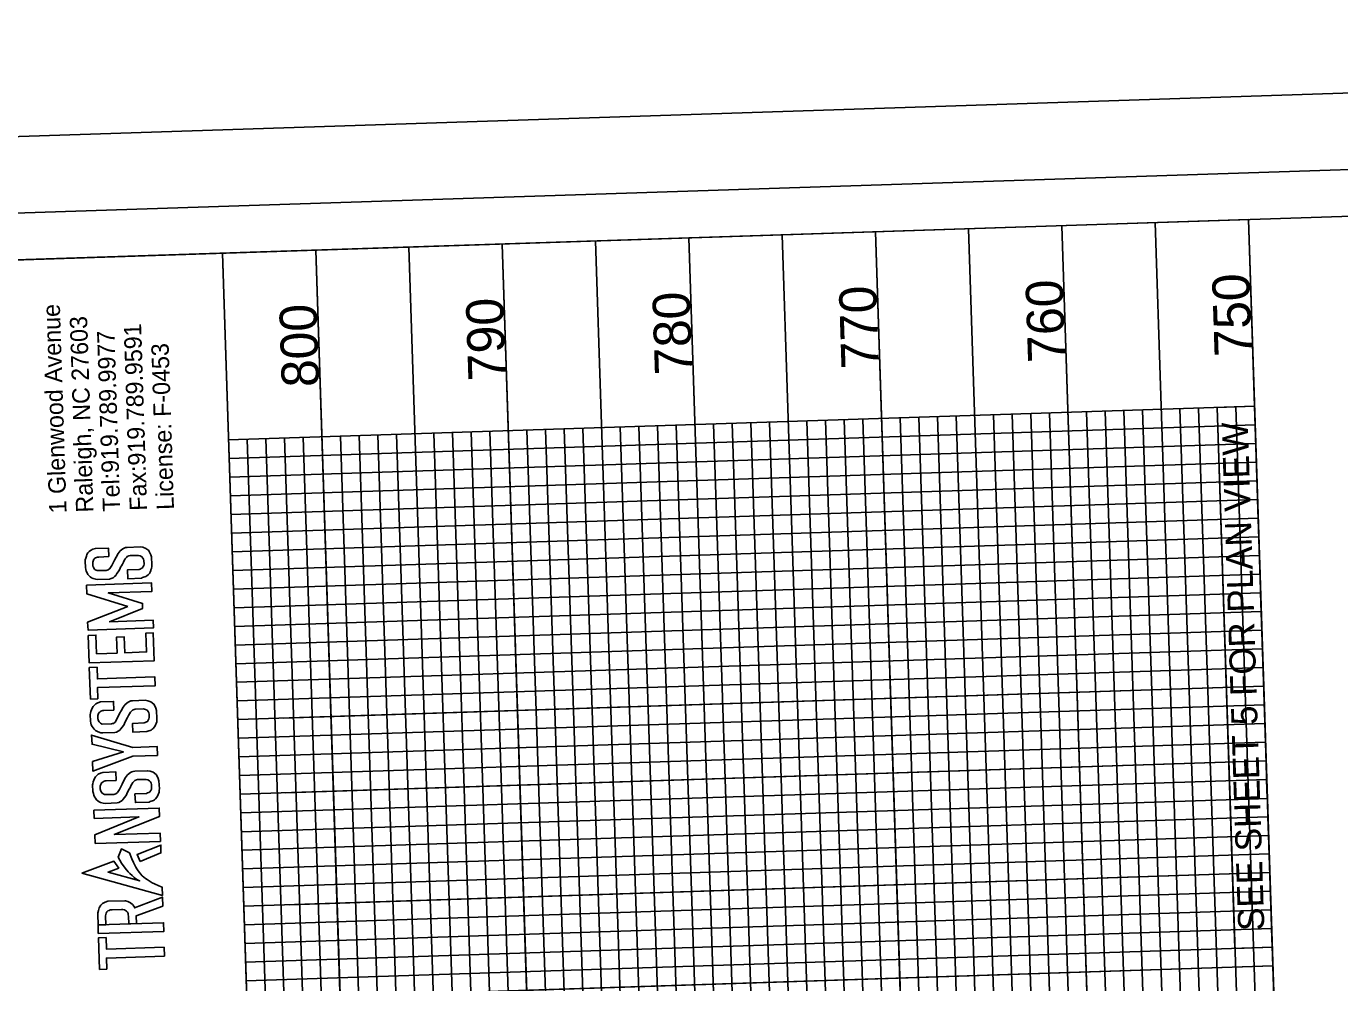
# Model space of a CAD drawing. Extents: x 1627314 to 1628469, y 762309 to 764247.
# Drawn here: x 1627512.6 to 1627864.5, y 763788.2 to 764044.4 of the extents above; entities that cross this region are included whole.
import ezdxf

# ---------------------------------------------------------------- set-up
doc = ezdxf.new("R2010")
doc.units = 0
for name, color, linetype in [('Exist Vertical Profile Vertical Axis Label', 7, 'Continuous'), ('Old_Level_2', 7, 'Continuous'), ('Prop DSN Text', 7, 'Continuous'), ('Prop Grid Mask', 7, 'Continuous'), ('Sheet DOT Grid CELL', 7, 'Continuous'), ('Sheet Layout Profile Border Port 1', 7, 'Continuous'), ('Sheet Plot Border Inside CELL', 7, 'Continuous'), ('Sheet Plot Border Outside CELL', 7, 'Continuous'), ('Sheet Profile CELL', 7, 'Continuous'), ('Sheet Profile Grid Major CELL', 7, 'Continuous'), ('Sheet Profile Grid Middle CELL', 7, 'Continuous'), ('Sheet Profile Grid Minor CELL', 7, 'Continuous')]:
    doc.layers.add(name, color=color, linetype=linetype)

msp = doc.modelspace()

# ---------------------------------------------------------------- linework, layer by layer
at = {"layer": 'Old_Level_2'}
for points in [[(1627507.79, 763781.61), (1627501.25, 763981.49), (1627565.16, 763983.58), (1627571.7, 763783.7)], [(1627534.7, 763902.32), (1627534.62, 763904.63), (1627531.15, 763904.51), (1627530.45, 763904.29), (1627529.87, 763903.99), (1627529.49, 763903.68), (1627529.15, 763903.3), (1627528.88, 763902.85), (1627528.72, 763902.42), (1627528.72, 763902.42), (1627528.54, 763901.95), (1627528.44, 763901.47), (1627528.37, 763901.14), (1627528.46, 763899.4), (1627528.57, 763898.87), (1627528.66, 763898.42), (1627528.92, 763897.96), (1627529.14, 763897.57), (1627529.44, 763897.18), (1627529.76, 763896.88), (1627530.13, 763896.65), (1627530.53, 763896.47), (1627531.24, 763896.24), (1627531.76, 763896.2), (1627534.92, 763896.31), (1627535.4, 763896.44), (1627535.88, 763896.68), (1627536.28, 763896.99), (1627536.58, 763897.29), (1627536.92, 763897.76), (1627537.25, 763898.22), (1627537.46, 763898.51), (1627537.67, 763899), (1627537.88, 763899.49), (1627538.12, 763899.89), (1627538.39, 763900.34), (1627538.64, 763900.87), (1627538.84, 763901.31), (1627539.14, 763901.75), (1627539.43, 763902.07), (1627539.66, 763902.33), (1627540.13, 763902.5), (1627540.43, 763902.6), (1627542.67, 763902.64), (1627543.16, 763902.5), (1627543.58, 763902.27), (1627543.88, 763901.95), (1627544.06, 763901.6), (1627544.14, 763901.26), (1627544.19, 763900.3), (1627544.11, 763899.97), (1627543.93, 763899.64), (1627543.75, 763899.3), (1627543.42, 763899.15), (1627543.09, 763899), (1627542.82, 763898.88), (1627539.71, 763898.74), (1627539.82, 763896.4), (1627543.52, 763896.57), (1627543.8, 763896.69), (1627544.65, 763896.99), (1627544.94, 763897.18), (1627545.25, 763897.44), (1627545.61, 763897.83), (1627545.8, 763898.14), (1627545.96, 763898.58), (1627546.03, 763898.74), (1627546.19, 763899.18), (1627546.23, 763899.72), (1627546.25, 763900.11), (1627546.13, 763902.25), (1627545.97, 763902.84), (1627545.57, 763903.65), (1627545.43, 763903.93), (1627544.62, 763904.52), (1627543.83, 763904.83), (1627543.11, 763904.96), (1627539.69, 763904.8), (1627539.22, 763904.77), (1627538.85, 763904.63), (1627538.5, 763904.43), (1627537.76, 763903.86), (1627537.23, 763903.14), (1627536.68, 763902.14), (1627536.26, 763901.39), (1627535.54, 763899.9), (1627535.01, 763899.13), (1627534.59, 763898.78), (1627534.31, 763898.7), (1627534.03, 763898.61), (1627531.6, 763898.58), (1627531.34, 763898.69), (1627531.08, 763898.81), (1627530.93, 763898.98), (1627530.72, 763899.21), (1627530.61, 763899.46), (1627530.49, 763899.72), (1627530.52, 763899.86), (1627530.44, 763899.88), (1627530.42, 763900.84), (1627530.53, 763901.12), (1627530.63, 763901.4), (1627530.73, 763901.68), (1627530.91, 763901.81), (1627531.19, 763902.01), (1627531.46, 763902.11), (1627531.73, 763902.21), (1627532.04, 763902.21)], [(1627539.83, 763888.95), (1627529.04, 763884.78), (1627529.22, 763882.58), (1627546.67, 763883.23), (1627546.59, 763885.34), (1627534.92, 763884.9), (1627543.79, 763888.46), (1627543.78, 763889.81), (1627534.56, 763892.58), (1627546.27, 763893), (1627546.19, 763895.28), (1627528.78, 763894.65), (1627528.86, 763892.35)], [(1627529.23, 763881.22), (1627529.48, 763873.84), (1627546.89, 763874.43), (1627546.64, 763881.9), (1627544.67, 763881.83), (1627544.84, 763876.79), (1627539, 763876.59), (1627538.86, 763880.8), (1627536.79, 763880.73), (1627536.93, 763876.49), (1627531.44, 763876.3), (1627531.27, 763881.31)], [(1627529.79, 763864.16), (1627529.51, 763872.62), (1627531.58, 763872.69), (1627531.69, 763869.58), (1627547.1, 763870.1), (1627547.18, 763867.75), (1627531.66, 763867.23), (1627531.76, 763864.26)], [(1627536.08, 763861.21), (1627536.01, 763863.52), (1627532.53, 763863.4), (1627531.83, 763863.18), (1627531.25, 763862.88), (1627530.87, 763862.57), (1627530.53, 763862.19), (1627530.26, 763861.74), (1627530.1, 763861.31), (1627530.1, 763861.31), (1627529.93, 763860.84), (1627529.82, 763860.36), (1627529.75, 763860.03), (1627529.84, 763858.29), (1627529.95, 763857.76), (1627530.04, 763857.31), (1627530.3, 763856.85), (1627530.52, 763856.46), (1627530.82, 763856.07), (1627531.14, 763855.77), (1627531.52, 763855.54), (1627531.92, 763855.36), (1627532.62, 763855.13), (1627533.14, 763855.09), (1627536.31, 763855.2), (1627536.78, 763855.33), (1627537.26, 763855.58), (1627537.67, 763855.88), (1627537.97, 763856.18), (1627538.3, 763856.65), (1627538.63, 763857.11), (1627538.84, 763857.4), (1627539.05, 763857.89), (1627539.26, 763858.38), (1627539.5, 763858.78), (1627539.77, 763859.23), (1627540.02, 763859.77), (1627540.23, 763860.21), (1627540.53, 763860.65), (1627540.81, 763860.96), (1627541.04, 763861.22), (1627541.52, 763861.39), (1627541.81, 763861.5), (1627544.05, 763861.53), (1627544.54, 763861.39), (1627544.97, 763861.16), (1627545.27, 763860.84), (1627545.44, 763860.49), (1627545.52, 763860.15), (1627545.57, 763859.19), (1627545.49, 763858.87), (1627545.31, 763858.53), (1627545.13, 763858.2), (1627544.8, 763858.04), (1627544.47, 763857.89), (1627544.21, 763857.77), (1627541.1, 763857.63), (1627541.2, 763855.29), (1627544.91, 763855.46), (1627545.19, 763855.58), (1627546.04, 763855.88), (1627546.32, 763856.07), (1627546.63, 763856.33), (1627547, 763856.72), (1627547.18, 763857.03), (1627547.35, 763857.48), (1627547.41, 763857.64), (1627547.58, 763858.07), (1627547.61, 763858.61), (1627547.64, 763859), (1627547.51, 763861.14), (1627547.35, 763861.73), (1627546.95, 763862.54), (1627546.82, 763862.82), (1627546.01, 763863.41), (1627545.21, 763863.72), (1627544.49, 763863.85), (1627541.08, 763863.69), (1627540.6, 763863.66), (1627540.23, 763863.52), (1627539.88, 763863.32), (1627539.14, 763862.75), (1627538.61, 763862.03), (1627538.06, 763861.04), (1627537.64, 763860.28), (1627536.92, 763858.79), (1627536.39, 763858.02), (1627535.98, 763857.67), (1627535.7, 763857.59), (1627535.42, 763857.5), (1627532.98, 763857.47), (1627532.73, 763857.58), (1627532.47, 763857.7), (1627532.31, 763857.87), (1627532.11, 763858.1), (1627531.99, 763858.35), (1627531.87, 763858.61), (1627531.9, 763858.75), (1627531.82, 763858.77), (1627531.81, 763859.73), (1627531.91, 763860.01), (1627532.01, 763860.29), (1627532.11, 763860.57), (1627532.3, 763860.7), (1627532.57, 763860.9), (1627532.84, 763861), (1627533.12, 763861.1), (1627533.42, 763861.1)], [(1627530.37, 763847.41), (1627530.45, 763844.88), (1627541.21, 763848.85), (1627547.75, 763849.09), (1627547.66, 763851.48), (1627541.17, 763851.24), (1627530.09, 763854.54), (1627530.24, 763852.05), (1627538.66, 763850.01)], [(1627536.72, 763842.35), (1627536.64, 763844.65), (1627533.16, 763844.54), (1627532.47, 763844.32), (1627531.89, 763844.02), (1627531.51, 763843.71), (1627531.17, 763843.33), (1627530.9, 763842.88), (1627530.74, 763842.45), (1627530.74, 763842.45), (1627530.56, 763841.98), (1627530.45, 763841.5), (1627530.38, 763841.17), (1627530.48, 763839.43), (1627530.59, 763838.9), (1627530.68, 763838.45), (1627530.93, 763837.99), (1627531.16, 763837.6), (1627531.46, 763837.21), (1627531.78, 763836.91), (1627532.15, 763836.68), (1627532.55, 763836.5), (1627533.26, 763836.27), (1627533.77, 763836.23), (1627536.94, 763836.34), (1627537.41, 763836.47), (1627537.9, 763836.71), (1627538.3, 763837.02), (1627538.6, 763837.32), (1627538.93, 763837.78), (1627539.27, 763838.25), (1627539.48, 763838.54), (1627539.69, 763839.03), (1627539.89, 763839.52), (1627540.13, 763839.92), (1627540.41, 763840.37), (1627540.66, 763840.9), (1627540.86, 763841.34), (1627541.16, 763841.78), (1627541.45, 763842.1), (1627541.68, 763842.36), (1627542.15, 763842.53), (1627542.45, 763842.63), (1627544.68, 763842.67), (1627545.17, 763842.53), (1627545.6, 763842.3), (1627545.9, 763841.98), (1627546.07, 763841.63), (1627546.16, 763841.29), (1627546.21, 763840.33), (1627546.13, 763840), (1627545.95, 763839.67), (1627545.76, 763839.33), (1627545.43, 763839.18), (1627545.1, 763839.03), (1627544.84, 763838.91), (1627541.73, 763838.77), (1627541.84, 763836.43), (1627545.54, 763836.6), (1627545.82, 763836.72), (1627546.67, 763837.02), (1627546.96, 763837.21), (1627547.27, 763837.47), (1627547.63, 763837.86), (1627547.81, 763838.17), (1627547.98, 763838.61), (1627548.04, 763838.77), (1627548.21, 763839.21), (1627548.25, 763839.75), (1627548.27, 763840.14), (1627548.15, 763842.28), (1627547.99, 763842.87), (1627547.59, 763843.68), (1627547.45, 763843.95), (1627546.64, 763844.55), (1627545.84, 763844.86), (1627545.13, 763844.99), (1627541.71, 763844.83), (1627541.24, 763844.8), (1627540.87, 763844.66), (1627540.52, 763844.46), (1627539.78, 763843.89), (1627539.24, 763843.17), (1627538.7, 763842.17), (1627538.28, 763841.42), (1627537.56, 763839.93), (1627537.02, 763839.15), (1627536.61, 763838.81), (1627536.33, 763838.73), (1627536.05, 763838.64), (1627533.62, 763838.61), (1627533.36, 763838.72), (1627533.1, 763838.84), (1627532.94, 763839.01), (1627532.74, 763839.23), (1627532.62, 763839.49), (1627532.51, 763839.75), (1627532.53, 763839.89), (1627532.46, 763839.91), (1627532.44, 763840.86), (1627532.54, 763841.15), (1627532.64, 763841.43), (1627532.74, 763841.71), (1627532.93, 763841.84), (1627533.2, 763842.04), (1627533.48, 763842.14), (1627533.75, 763842.24), (1627534.06, 763842.24)], [(1627531.1, 763825.45), (1627548.55, 763826.04), (1627548.47, 763828.28), (1627536.2, 763827.86), (1627548.35, 763832.72), (1627548.25, 763834.96), (1627530.75, 763834.37), (1627530.83, 763832.19), (1627542.8, 763832.6), (1627531.01, 763827.81)], [(1627527.54, 763817.56), (1627549.08, 763811.6), (1627548.99, 763813.82), (1627548.14, 763814.14), (1627546.97, 763814.67), (1627546.33, 763814.96), (1627545.78, 763815.32), (1627545, 763815.82), (1627544.52, 763816.13), (1627544.12, 763816.5), (1627543.71, 763816.86), (1627543.2, 763817.33), (1627542.92, 763817.74), (1627542.57, 763818.14), (1627542.23, 763818.69), (1627541.93, 763819.17), (1627541.33, 763820.37), (1627540.88, 763821.35), (1627540.27, 763822.98), (1627538.09, 763824.04), (1627537.21, 763821.84), (1627538.15, 763820.23), (1627539.1, 763818.89), (1627539.92, 763817.93), (1627540.37, 763817.42), (1627540.95, 763816.91), (1627541.54, 763816.39), (1627541.97, 763816.01), (1627542.63, 763815.65), (1627543, 763815.45), (1627534.54, 763817.81), (1627537.4, 763818.9), (1627536.08, 763820.75)], [(1627543.15, 763820.69), (1627542.32, 763822.58), (1627548.68, 763825.05), (1627548.67, 763822.95)], [(1627533.93, 763803.74), (1627533.85, 763806.13), (1627533.89, 763806.43), (1627534.04, 763806.84), (1627534.24, 763807.17), (1627534.51, 763807.41), (1627534.83, 763807.58), (1627535.09, 763807.71), (1627535.67, 763807.73), (1627538.16, 763807.82), (1627538.49, 763807.77), (1627538.94, 763807.7), (1627539.23, 763807.58), (1627539.5, 763807.38), (1627539.72, 763807.12), (1627539.89, 763806.7), (1627539.94, 763806.38), (1627539.99, 763806.05), (1627540.07, 763803.95), (1627542.18, 763804.03), (1627542.1, 763806.13), (1627549.18, 763808.74), (1627549.07, 763811.15), (1627541.63, 763808.25), (1627541.48, 763808.63), (1627541.06, 763809.15), (1627540.51, 763809.62), (1627539.87, 763809.95), (1627539.23, 763810.14), (1627539.04, 763810.12), (1627534.48, 763810.01), (1627533.74, 763809.79), (1627533.08, 763809.4), (1627532.62, 763808.98), (1627532.17, 763808.26), (1627531.96, 763807.58), (1627531.76, 763806.89), (1627531.77, 763806.49), (1627531.84, 763803.67)], [(1627531.92, 763801.36), (1627531.84, 763803.67), (1627549.4, 763804.26), (1627549.48, 763801.95)], [(1627532.23, 763791.74), (1627531.95, 763800.2), (1627534.02, 763800.27), (1627534.12, 763797.16), (1627549.54, 763797.68), (1627549.62, 763795.33), (1627534.1, 763794.81), (1627534.2, 763791.84)]]:
    msp.add_lwpolyline(points, close=True, dxfattribs=at)
at = {"layer": 'Prop Grid Mask'}
msp.add_lwpolyline([(1627831.66, 763942.29), (1627836.4, 763797.36), (1627846.39, 763797.69), (1627841.65, 763942.61)], close=True, dxfattribs=at)
at = {"layer": 'Sheet DOT Grid CELL'}
for p, q in [((1627740.07, 763989.32), (1627789.11, 762490.12)), ((1627790.04, 763990.95), (1627839.08, 762491.75)), ((1627640.12, 763986.05), (1627689.16, 762486.85)), ((1627690.1, 763987.68), (1627739.13, 762488.48)), ((1627590.15, 763984.41), (1627639.19, 762485.21)), ((1627841.65, 763942.61), (1627566.8, 763933.62)), ((1627843.28, 763892.64), (1627568.43, 763883.65)), ((1627844.92, 763842.67), (1627570.07, 763833.68)), ((1627846.55, 763792.69), (1627484.3, 763780.84))]:
    msp.add_line(p, q, dxfattribs=at)
at = {"layer": 'Sheet Layout Profile Border Port 1'}
msp.add_lwpolyline([(1627548.65, 762532.28), (1627887.42, 762543.36), (1627841.65, 763942.61), (1627566.8, 763933.62)], dxfattribs=at)
at = {"layer": 'Sheet Plot Border Inside CELL'}
msp.add_lwpolyline([(1628446.34, 762357.53), (1628391.86, 764023.14), (1627337.33, 763988.65), (1627391.81, 762323.04)], close=True, dxfattribs=at)
at = {"layer": 'Sheet Plot Border Outside CELL'}
msp.add_lwpolyline([(1628469.21, 762345.27), (1628413.63, 764044.37), (1627314.22, 764008.4), (1627369.79, 762309.31)], close=True, dxfattribs=at)
at = {"layer": 'Sheet Profile CELL'}
msp.add_line((1627889.05, 762493.39), (1627840.02, 763992.59), dxfattribs=at)
msp.add_lwpolyline([(1627340.28, 763976.24), (1627389.32, 762477.04), (1628438.76, 762511.37), (1628389.72, 764010.57)], close=True, dxfattribs=at)
at = {"layer": 'Sheet Profile Grid Major CELL'}
for points in [[(1627566.8, 763933.62), (1627841.65, 763942.61), (1627840.02, 763992.59), (1627490.2, 763981.14)], [(1627740.07, 763989.32), (1627789.11, 762490.12), (1627789.11, 762490.12), (1627839.08, 762491.75), (1627790.04, 763990.95)], [(1627640.12, 763986.05), (1627689.16, 762486.85), (1627739.13, 762488.48), (1627690.1, 763987.68)], [(1627546.71, 763782.88), (1627589.21, 762483.58), (1627639.19, 762485.21), (1627590.15, 763984.41)], [(1627570.07, 763833.68), (1627844.92, 763842.67), (1627843.28, 763892.64), (1627843.28, 763892.64), (1627568.43, 763883.65)], [(1627363.17, 763276.61), (1627361.53, 763326.59), (1627861.27, 763342.93), (1627859.63, 763392.91), (1627359.9, 763376.56), (1627358.26, 763426.53), (1627858, 763442.88), (1627856.36, 763492.85), (1627356.63, 763476.51), (1627354.99, 763526.48), (1627854.73, 763542.83), (1627853.09, 763592.8), (1627353.36, 763576.45), (1627351.73, 763626.43), (1627851.46, 763642.77), (1627849.82, 763692.75), (1627350.09, 763676.4), (1627348.46, 763726.37), (1627848.19, 763742.72), (1627846.55, 763792.69), (1627346.82, 763776.35), (1627345.96, 763802.63)]]:
    msp.add_lwpolyline(points, dxfattribs=at)
at = {"layer": 'Sheet Profile Grid Middle CELL'}
for points in [[(1627715.08, 763988.5), (1627764.12, 762489.3), (1627814.09, 762490.94), (1627765.06, 763990.13)], [(1627815.03, 763991.77), (1627864.07, 762492.57)], [(1627615.14, 763985.23), (1627664.17, 762486.03), (1627714.15, 762487.67), (1627665.11, 763986.86)], [(1627570.88, 763808.69), (1627565.16, 763983.6)], [(1627581.44, 763859.06), (1627844.1, 763867.65), (1627842.47, 763917.63), (1627567.61, 763908.64)], [(1627583.08, 763809.09), (1627845.74, 763817.68), (1627844.1, 763867.65), (1627569.25, 763858.66)], [(1627863.72, 763267.97), (1627862.08, 763317.95), (1627362.35, 763301.6), (1627360.72, 763351.57), (1627860.45, 763367.92), (1627858.81, 763417.89), (1627359.08, 763401.55), (1627357.45, 763451.52), (1627857.18, 763467.87), (1627855.54, 763517.84), (1627355.81, 763501.49), (1627354.18, 763551.47), (1627853.91, 763567.81), (1627852.28, 763617.79), (1627352.54, 763601.44), (1627350.91, 763651.41), (1627850.64, 763667.76), (1627849.01, 763717.73), (1627349.27, 763701.39), (1627347.64, 763751.36), (1627847.37, 763767.71), (1627845.74, 763817.68), (1627570.88, 763808.69)], [(1627521.73, 763782.02), (1627564.23, 762482.76), (1627614.2, 762484.4), (1627570.88, 763808.69)]]:
    msp.add_lwpolyline(points, dxfattribs=at)
at = {"layer": 'Sheet Profile Grid Minor CELL'}
for p, q in [((1627751.7, 763939.67), (1627797.47, 762540.42)), ((1627802.47, 762540.58), (1627756.7, 763939.83)), ((1627761.69, 763940), (1627807.46, 762540.75)), ((1627817.46, 762541.07), (1627771.69, 763940.32)), ((1627776.69, 763940.49), (1627822.45, 762541.24)), ((1627827.45, 762541.4), (1627781.68, 763940.65)), ((1627786.68, 763940.81), (1627832.45, 762541.56)), ((1627842.44, 762541.89), (1627796.67, 763941.14)), ((1627801.67, 763941.3), (1627847.44, 762542.05)), ((1627852.44, 762542.22), (1627806.67, 763941.47)), ((1627811.67, 763941.63), (1627857.44, 762542.38)), ((1627867.43, 762542.71), (1627821.66, 763941.96)), ((1627826.66, 763942.12), (1627872.43, 762542.87)), ((1627877.42, 762543.03), (1627831.66, 763942.29)), ((1627692.52, 762536.99), (1627646.75, 763936.24)), ((1627651.75, 763936.4), (1627697.52, 762537.15)), ((1627702.52, 762537.31), (1627656.75, 763936.56)), ((1627661.75, 763936.73), (1627707.52, 762537.48)), ((1627717.51, 762537.8), (1627671.74, 763937.05)), ((1627676.74, 763937.22), (1627722.51, 762537.97)), ((1627727.51, 762538.13), (1627681.74, 763937.38)), ((1627686.73, 763937.55), (1627732.5, 762538.29)), ((1627742.5, 762538.62), (1627696.73, 763937.87)), ((1627701.73, 763938.04), (1627747.49, 762538.78)), ((1627752.49, 762538.95), (1627706.72, 763938.2)), ((1627711.72, 763938.36), (1627757.49, 762539.11)), ((1627767.48, 762539.44), (1627721.71, 763938.69)), ((1627726.71, 763938.85), (1627772.48, 762539.6)), ((1627731.71, 763939.02), (1627777.48, 762539.76)), ((1627736.71, 763939.18), (1627782.48, 762539.93)), ((1627792.47, 762540.25), (1627746.7, 763939.51)), ((1627576.79, 763933.95), (1627622.56, 762534.7)), ((1627627.56, 762534.86), (1627581.79, 763934.11)), ((1627586.79, 763934.28), (1627632.56, 762535.02)), ((1627642.55, 762535.35), (1627596.78, 763934.6)), ((1627601.78, 763934.77), (1627647.55, 762535.51)), ((1627652.55, 762535.68), (1627606.78, 763934.93)), ((1627611.77, 763935.09), (1627657.54, 762535.84)), ((1627667.54, 762536.17), (1627621.77, 763935.42)), ((1627626.77, 763935.58), (1627672.53, 762536.33)), ((1627677.53, 762536.5), (1627631.76, 763935.75)), ((1627636.76, 763935.91), (1627682.53, 762536.66))]:
    msp.add_line(p, q, dxfattribs=at)
for points in [[(1627836.65, 763942.45), (1627882.42, 762543.2)], [(1627567.12, 763923.63), (1627841.98, 763932.62), (1627841.81, 763937.62), (1627566.96, 763928.62)], [(1627566.71, 763783.49), (1627607.57, 762534.21), (1627617.56, 762534.53), (1627571.79, 763933.79)], [(1627567.45, 763913.63), (1627842.3, 763922.62), (1627842.14, 763927.62), (1627567.29, 763918.63)], [(1627567.94, 763898.64), (1627842.79, 763907.63), (1627842.63, 763912.63), (1627567.78, 763903.64)], [(1627568.27, 763888.65), (1627843.12, 763897.64), (1627842.96, 763902.63), (1627568.1, 763893.64)], [(1627568.76, 763873.65), (1627843.61, 763882.64), (1627843.45, 763887.64), (1627568.6, 763878.65)], [(1627569.09, 763863.66), (1627843.94, 763872.65), (1627843.78, 763877.65), (1627568.92, 763868.66)], [(1627569.58, 763848.67), (1627844.43, 763857.66), (1627844.27, 763862.66), (1627569.41, 763853.66)], [(1627582.1, 763839.07), (1627844.76, 763847.66), (1627844.59, 763852.66), (1627569.74, 763843.67)], [(1627570.23, 763828.65), (1627845.04, 763837.57), (1627844.87, 763842.56), (1627844.76, 763847.66), (1627569.9, 763838.67)], [(1627570.72, 763813.69), (1627845.57, 763822.68), (1627845.57, 763822.68), (1627845.41, 763827.67), (1627845.25, 763832.67), (1627570.39, 763823.68)], [(1627570.56, 763818.68), (1627845.41, 763827.67)], [(1627571.21, 763798.69), (1627846.06, 763807.68), (1627845.9, 763812.68), (1627571.05, 763803.69)], [(1627571.54, 763788.7), (1627846.39, 763797.69), (1627846.23, 763802.69), (1627571.37, 763793.7)]]:
    msp.add_lwpolyline(points, dxfattribs=at)

# ---------------------------------------------------------------- texts
at = {"layer": 'Exist Vertical Profile Vertical Axis Label'}
for s, p in [('760', (1627790.99, 763954.39)), ('750', (1627840.96, 763956.03)), ('780', (1627691.04, 763951.13)), ('770', (1627741.01, 763952.76)), ('800', (1627591.09, 763947.86)), ('790', (1627641.07, 763949.49))]:
    msp.add_text(s, height=10, rotation=91.8735, dxfattribs=at).set_placement(p)
at = {"layer": 'Old_Level_2'}
for s, p in [('1 Glenwood Avenue', (1627523.43, 763913.98)), ('Raleigh, NC 27603', (1627530.62, 763914.21)), ('Fax:919.789.9591', (1627545.01, 763914.68)), ('Tel:919.789.9977 ', (1627537.81, 763914.45)), ('License: F-0453', (1627552.2, 763914.92))]:
    msp.add_text(s, height=4.6576, rotation=91.8735, dxfattribs=at).set_placement(p)
at = {"layer": 'Prop DSN Text'}
msp.add_text('SEE SHEET 5 FOR PLAN VIEW', height=7, rotation=91.8735, dxfattribs=at).set_placement((1627844.29, 763802.2))

doc.saveas('drawing.dxf')
